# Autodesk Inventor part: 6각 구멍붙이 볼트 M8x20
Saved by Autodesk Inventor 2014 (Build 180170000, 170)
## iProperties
Created: 2025-06
Part Number: 6각 구멍붙이 볼트 M8x20
Material: 일반
Document SubType Name: Modeling
Designer: dg
Density: 1 g/cm^3
Appearance: 기본값
Author: dg
Author: jhkim
Description: 6각머리 태핑 나사
Creation Date: 2025-06-19
Sending System: Autodesk Inventor 2026
Preprocessor: ST-DEVELOPER v20.1
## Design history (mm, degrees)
node "6각 구멍붙이 볼트 M8x201"
body "Solid1"
node "기준1"
